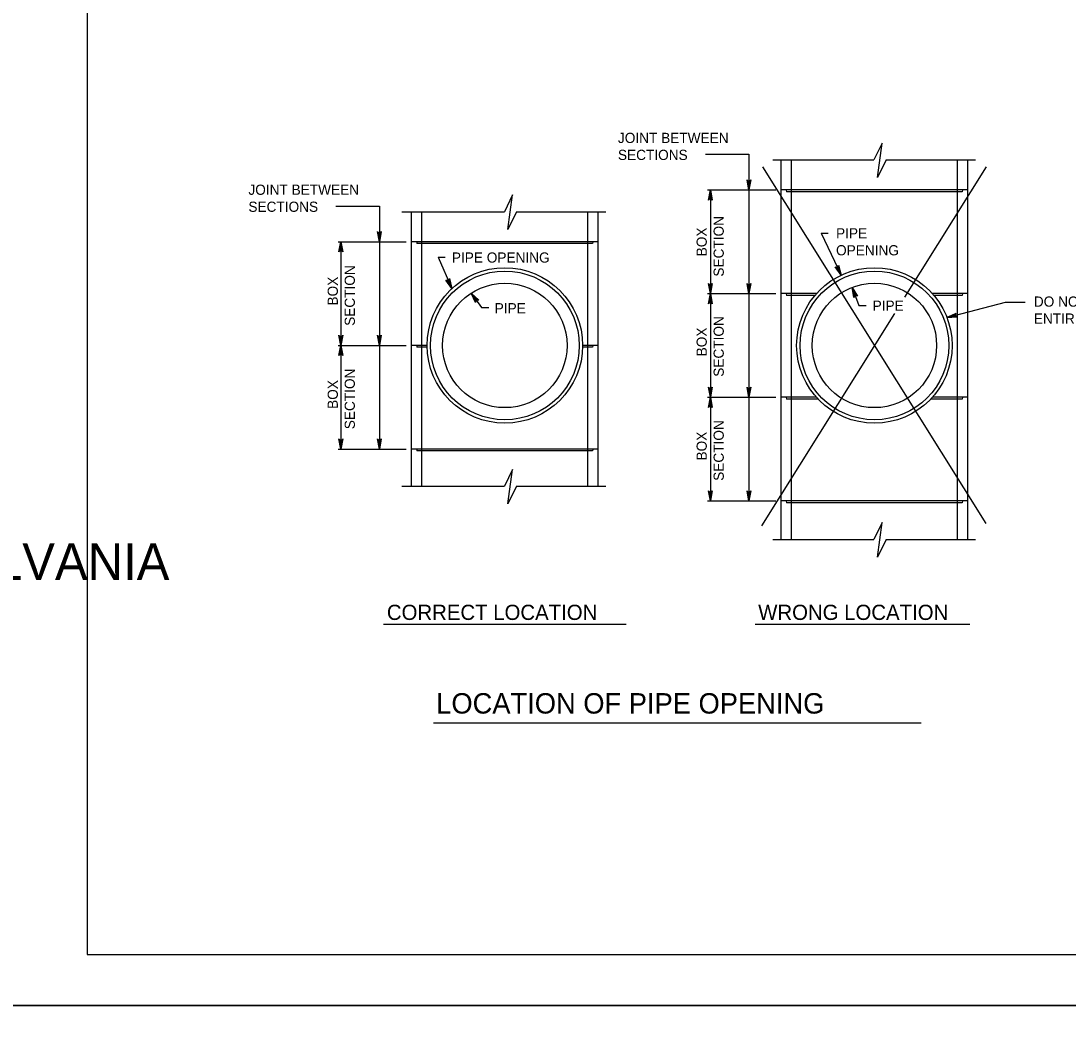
# Model space of a CAD drawing. Extents: x -6420 to 49575, y -4552 to 11624.
# Drawn here: x -838 to 172, y 5753 to 6727 of the extents above; entities that cross this region are included whole.
import ezdxf

# ---------------------------------------------------------------- set-up
doc = ezdxf.new("R2010")
doc.units = 0
doc.layers.add('1', color=7, linetype='Continuous')
doc.layers.add('PLT-BNDY', color=7, linetype='Continuous')

msp = doc.modelspace()

# ---------------------------------------------------------------- linework, layer by layer
at = {"layer": '1'}
for p, q in [((-177.6, 6598.6), (-135.7, 6598.6)), ((-135.7, 6598.6), (-135.7, 6264.2)), ((-122.6, 6586.4), (92.8, 6242.6)), ((-112.8, 6593.2), (-15.1, 6593.2)), ((-104.7, 6227.1), (-104.7, 6593.2)), ((-94.7, 6227.1), (-94.7, 6593.2)), ((-3.5, 6593.2), (82.7, 6593.2)), ((93.1, 6586.4), (14.4, 6460.7)), ((65.3, 6227.1), (65.3, 6593.2)), ((75.3, 6227.1), (75.3, 6593.2)), ((-175.6, 6564.2), (-109.7, 6564.2)), ((-172.9, 6564.2), (-172.9, 6464.2)), ((75.3, 6564.2), (-104.7, 6564.2)), ((-99.7, 6564.2), (-99.5, 6562.5)), ((70.1, 6562.5), (-99.5, 6562.5)), ((70.3, 6564.2), (70.1, 6562.5)), ((-534.2, 6548.6), (-492.2, 6548.6)), ((-492.2, 6548.6), (-492.2, 6314.2)), ((-470.6, 6543.2), (-371.6, 6543.2)), ((-461.2, 6278.4), (-461.2, 6543.2)), ((-451.2, 6278.4), (-451.2, 6543.2)), ((-360, 6543.2), (-273.7, 6543.2)), ((-291.2, 6278.4), (-291.2, 6543.2)), ((-281.2, 6278.4), (-281.2, 6543.2)), ((-66.1, 6522.5), (-59.3, 6522.5)), ((-66.1, 6522.5), (-46.9, 6482)), ((-532.1, 6514.2), (-466.3, 6514.2)), ((-529.5, 6514.2), (-529.5, 6414.2)), ((-281.2, 6514.2), (-461.2, 6514.2)), ((-456.2, 6514.2), (-456, 6512.5)), ((-286.5, 6512.5), (-456, 6512.5)), ((-286.2, 6514.2), (-286.5, 6512.5)), ((-435.6, 6499.4), (-428.8, 6499.4)), ((-435.6, 6499.4), (-422.4, 6469.1)), ((-36.3, 6470.2), (-29.6, 6452.9)), ((-403.7, 6464.7), (-393.6, 6450.9)), ((-175.6, 6464.2), (-109.7, 6464.2)), ((-172.9, 6464.2), (-172.9, 6364.2)), ((-70.6, 6464.2), (-104.7, 6464.2)), ((-99.7, 6464.2), (-99.5, 6462.5)), ((-72.1, 6462.5), (-99.5, 6462.5)), ((75.3, 6464.2), (41.2, 6464.2)), ((70.1, 6462.5), (42.6, 6462.5)), ((70.3, 6464.2), (70.1, 6462.5)), ((-393.6, 6450.9), (-386.8, 6450.9)), ((4.6, 6445.1), (-123.7, 6240.2)), ((-29.6, 6452.9), (-22.7, 6452.9)), ((-532.1, 6414.2), (-466.3, 6414.2)), ((-529.5, 6414.2), (-529.5, 6314.2)), ((-446.2, 6414.2), (-461.2, 6414.2)), ((-456.2, 6414.2), (-456, 6412.5)), ((-446.2, 6412.5), (-456, 6412.5)), ((-286.5, 6412.5), (-296.3, 6412.5)), ((-281.2, 6414.2), (-296.2, 6414.2)), ((-286.2, 6414.2), (-286.5, 6412.5)), ((-175.6, 6364.2), (-109.7, 6364.2)), ((-172.9, 6364.2), (-172.9, 6264.2)), ((-70.6, 6364.2), (-104.7, 6364.2)), ((-99.7, 6364.2), (-99.5, 6362.5)), ((75.3, 6364.2), (41.2, 6364.2)), ((70.3, 6364.2), (70.1, 6362.5)), ((-69.1, 6362.5), (-99.5, 6362.5)), ((70.1, 6362.5), (39.6, 6362.5)), ((-532.1, 6314.2), (-466.3, 6314.2)), ((-281.2, 6314.2), (-461.2, 6314.2)), ((-456.2, 6314.2), (-456, 6312.5)), ((-286.2, 6314.2), (-286.5, 6312.5)), ((-286.5, 6312.5), (-456, 6312.5)), ((-470.6, 6278.4), (-371.6, 6278.4)), ((-360, 6278.4), (-273.7, 6278.4)), ((-175.6, 6264.2), (-109.7, 6264.2)), ((75.3, 6264.2), (-104.7, 6264.2)), ((-99.7, 6264.2), (-99.5, 6262.5)), ((70.3, 6264.2), (70.1, 6262.5)), ((70.1, 6262.5), (-99.5, 6262.5)), ((-112.8, 6227.1), (-15.1, 6227.1)), ((-3.5, 6227.1), (82.7, 6227.1)), ((-488.3, 6145.2), (-254.3, 6145.2)), ((-129.6, 6145.2), (77.3, 6145.2)), ((-439.9, 6050.2), (30.4, 6050.2))]:
    msp.add_line(p, q, dxfattribs=at)
for points in [[(1804.7, 5826.7), (1804.7, 7677), (-774, 7677), (-774, 5826.7), (1804.7, 5826.7), (1804.7, 5913.1), (1148.5, 5913.1), (1148.5, 6125.3), (1804.7, 6125.3), (1804.7, 6220.4), (1148.5, 6220.4), (1148.5, 5826.7), (1407.1, 5826.7), (1407.1, 5913.1), (1407.1, 5826.7), (1659.7, 5826.7), (1659.7, 5913.1), (1659.7, 5872.7), (1804.7, 5872.7)], [(-3.5, 6593.2), (-11.8, 6576.1), (-7.3, 6609.4), (-15.1, 6593.2)], [(-135.7, 6564.2), (-137.5, 6574), (-137.3, 6573.6), (-137, 6573.2), (-136.7, 6573), (-136.3, 6572.9), (-136, 6572.8), (-135.7, 6572.7), (-135.4, 6572.8), (-135, 6572.9), (-134.7, 6573), (-134.4, 6573.2), (-134.1, 6573.6), (-133.8, 6574), (-135.7, 6564.2), (-134.1, 6573.6), (-134.4, 6573.2), (-135.7, 6564.2), (-134.7, 6573), (-135, 6572.9), (-135.7, 6564.2), (-135.4, 6572.8), (-135.7, 6572.7), (-135.7, 6564.2), (-136, 6572.8), (-136.3, 6572.9), (-135.7, 6564.2), (-136.7, 6573), (-137, 6573.2), (-135.7, 6564.2), (-137.3, 6573.6)], [(-360, 6543.2), (-368.4, 6526.1), (-363.8, 6559.4), (-371.6, 6543.2)], [(-172.9, 6564.2), (-171.1, 6554.4), (-171.4, 6554.8), (-171.6, 6555.2), (-171.9, 6555.4), (-172.3, 6555.6), (-172.6, 6555.6), (-172.9, 6555.7), (-173.3, 6555.6), (-173.6, 6555.6), (-173.9, 6555.4), (-174.2, 6555.2), (-174.5, 6554.8), (-174.8, 6554.4), (-172.9, 6564.2), (-174.5, 6554.8), (-174.2, 6555.2), (-172.9, 6564.2), (-173.9, 6555.4), (-173.6, 6555.6), (-172.9, 6564.2), (-173.3, 6555.6), (-172.9, 6555.7), (-172.9, 6564.2), (-172.6, 6555.6), (-172.3, 6555.6), (-172.9, 6564.2), (-171.9, 6555.4), (-171.6, 6555.2), (-172.9, 6564.2), (-171.4, 6554.8)], [(-492.2, 6514.2), (-494, 6524), (-493.8, 6523.6), (-493.5, 6523.2), (-493.2, 6523), (-492.9, 6522.9), (-492.5, 6522.8), (-492.2, 6522.7), (-491.9, 6522.8), (-491.6, 6522.9), (-491.2, 6523), (-490.9, 6523.2), (-490.6, 6523.6), (-490.4, 6524), (-492.2, 6514.2), (-490.6, 6523.6), (-490.9, 6523.2), (-492.2, 6514.2), (-491.2, 6523), (-491.6, 6522.9), (-492.2, 6514.2), (-491.9, 6522.8), (-492.2, 6522.7), (-492.2, 6514.2), (-492.5, 6522.8), (-492.9, 6522.9), (-492.2, 6514.2), (-493.2, 6523), (-493.5, 6523.2), (-492.2, 6514.2), (-493.8, 6523.6)], [(-529.5, 6514.2), (-527.6, 6504.4), (-527.9, 6504.8), (-528.1, 6505.2), (-528.5, 6505.4), (-528.8, 6505.6), (-529.1, 6505.6), (-529.5, 6505.7), (-529.8, 6505.6), (-530.1, 6505.6), (-530.4, 6505.4), (-530.8, 6505.2), (-531, 6504.8), (-531.3, 6504.4), (-529.5, 6514.2), (-531, 6504.8), (-530.8, 6505.2), (-529.5, 6514.2), (-530.4, 6505.4), (-530.1, 6505.6), (-529.5, 6514.2), (-529.8, 6505.6), (-529.5, 6505.7), (-529.5, 6514.2), (-529.1, 6505.6), (-528.8, 6505.6), (-529.5, 6514.2), (-528.5, 6505.4), (-528.1, 6505.2), (-529.5, 6514.2), (-527.9, 6504.8)], [(-46.9, 6482), (-52.7, 6490), (-52.3, 6489.8), (-51.9, 6489.6), (-51.6, 6489.5), (-51.2, 6489.5), (-50.9, 6489.6), (-50.5, 6489.7), (-50.3, 6489.9), (-50, 6490.1), (-49.8, 6490.4), (-49.6, 6490.7), (-49.5, 6491.1), (-49.4, 6491.6), (-46.9, 6482), (-49.5, 6491.1), (-49.6, 6490.7), (-46.9, 6482), (-49.8, 6490.4), (-50, 6490.1), (-46.9, 6482), (-50.3, 6489.9), (-50.5, 6489.7), (-46.9, 6482), (-50.9, 6489.6), (-51.2, 6489.5), (-46.9, 6482), (-51.6, 6489.5), (-51.9, 6489.6), (-46.9, 6482), (-52.3, 6489.8)], [(-422.4, 6469.1), (-428, 6477.3), (-427.6, 6477.1), (-427.2, 6476.8), (-426.8, 6476.8), (-426.5, 6476.7), (-426.1, 6476.8), (-425.8, 6476.9), (-425.5, 6477.1), (-425.2, 6477.2), (-425, 6477.6), (-424.8, 6477.9), (-424.7, 6478.3), (-424.6, 6478.8), (-422.4, 6469.1), (-424.7, 6478.3), (-424.8, 6477.9), (-422.4, 6469.1), (-425, 6477.6), (-425.2, 6477.2), (-422.4, 6469.1), (-425.5, 6477.1), (-425.8, 6476.9), (-422.4, 6469.1), (-426.1, 6476.8), (-426.5, 6476.7), (-422.4, 6469.1), (-426.8, 6476.8), (-427.2, 6476.8), (-422.4, 6469.1), (-427.6, 6477.1)], [(-172.9, 6464.2), (-174.8, 6474), (-174.5, 6473.6), (-174.2, 6473.2), (-173.9, 6473), (-173.6, 6472.9), (-173.3, 6472.8), (-172.9, 6472.7), (-172.6, 6472.8), (-172.3, 6472.9), (-171.9, 6473), (-171.6, 6473.2), (-171.4, 6473.6), (-171.1, 6474), (-172.9, 6464.2), (-171.4, 6473.6), (-171.6, 6473.2), (-172.9, 6464.2), (-171.9, 6473), (-172.3, 6472.9), (-172.9, 6464.2), (-172.6, 6472.8), (-172.9, 6472.7), (-172.9, 6464.2), (-173.3, 6472.8), (-173.6, 6472.9), (-172.9, 6464.2), (-173.9, 6473), (-174.2, 6473.2), (-172.9, 6464.2), (-174.5, 6473.6)], [(-135.7, 6464.2), (-137.5, 6474), (-137.3, 6473.6), (-137, 6473.2), (-136.7, 6473), (-136.3, 6472.9), (-136, 6472.8), (-135.7, 6472.7), (-135.4, 6472.8), (-135, 6472.9), (-134.7, 6473), (-134.4, 6473.2), (-134.1, 6473.6), (-133.8, 6474), (-135.7, 6464.2), (-134.1, 6473.6), (-134.4, 6473.2), (-135.7, 6464.2), (-134.7, 6473), (-135, 6472.9), (-135.7, 6464.2), (-135.4, 6472.8), (-135.7, 6472.7), (-135.7, 6464.2), (-136, 6472.8), (-136.3, 6472.9), (-135.7, 6464.2), (-136.7, 6473), (-137, 6473.2), (-135.7, 6464.2), (-137.3, 6473.6)], [(-36.3, 6470.2), (-31, 6461.7), (-31.4, 6462), (-31.8, 6462.3), (-32.2, 6462.3), (-32.5, 6462.4), (-32.9, 6462.3), (-33.2, 6462.3), (-33.5, 6462.1), (-33.8, 6461.9), (-34, 6461.6), (-34.2, 6461.3), (-34.3, 6460.9), (-34.5, 6460.4), (-36.3, 6470.2), (-34.3, 6460.9), (-34.2, 6461.3), (-36.3, 6470.2), (-34, 6461.6), (-33.8, 6461.9), (-36.3, 6470.2), (-33.5, 6462.1), (-33.2, 6462.3), (-36.3, 6470.2), (-32.9, 6462.3), (-32.5, 6462.4), (-36.3, 6470.2), (-32.2, 6462.3), (-31.8, 6462.3), (-36.3, 6470.2), (-31.4, 6462)], [(-403.7, 6464.7), (-396.4, 6457.9), (-396.9, 6458), (-397.3, 6458.2), (-397.7, 6458.1), (-398, 6458.1), (-398.3, 6458), (-398.6, 6457.8), (-398.9, 6457.6), (-399.1, 6457.3), (-399.3, 6457), (-399.4, 6456.6), (-399.4, 6456.2), (-399.4, 6455.7), (-403.7, 6464.7), (-399.4, 6456.2), (-399.4, 6456.6), (-403.7, 6464.7), (-399.3, 6457), (-399.1, 6457.3), (-403.7, 6464.7), (-398.9, 6457.6), (-398.6, 6457.8), (-403.7, 6464.7), (-398.3, 6458), (-398, 6458.1), (-403.7, 6464.7), (-397.7, 6458.1), (-397.3, 6458.2), (-403.7, 6464.7), (-396.9, 6458)], [(-172.9, 6464.2), (-171.1, 6454.4), (-171.4, 6454.8), (-171.6, 6455.2), (-171.9, 6455.4), (-172.3, 6455.6), (-172.6, 6455.6), (-172.9, 6455.7), (-173.3, 6455.6), (-173.6, 6455.6), (-173.9, 6455.4), (-174.2, 6455.2), (-174.5, 6454.8), (-174.8, 6454.4), (-172.9, 6464.2), (-174.5, 6454.8), (-174.2, 6455.2), (-172.9, 6464.2), (-173.9, 6455.4), (-173.6, 6455.6), (-172.9, 6464.2), (-173.3, 6455.6), (-172.9, 6455.7), (-172.9, 6464.2), (-172.6, 6455.6), (-172.3, 6455.6), (-172.9, 6464.2), (-171.9, 6455.4), (-171.6, 6455.2), (-172.9, 6464.2), (-171.4, 6454.8)], [(55.3, 6441.1), (111.7, 6455.8), (130.8, 6455.8)], [(55.3, 6441.1), (64.2, 6445.3), (63.9, 6445), (63.6, 6444.6), (63.5, 6444.2), (63.4, 6443.9), (63.5, 6443.6), (63.5, 6443.2), (63.6, 6442.9), (63.8, 6442.6), (64, 6442.4), (64.3, 6442.1), (64.7, 6441.9), (65.2, 6441.8), (55.3, 6441.1), (64.7, 6441.9), (64.3, 6442.1), (55.3, 6441.1), (64, 6442.4), (63.8, 6442.6), (55.3, 6441.1), (63.6, 6442.9), (63.5, 6443.2), (55.3, 6441.1), (63.5, 6443.6), (63.4, 6443.9), (55.3, 6441.1), (63.5, 6444.2), (63.6, 6444.6), (55.3, 6441.1), (63.9, 6445)], [(-529.5, 6414.2), (-531.3, 6424), (-531, 6423.6), (-530.8, 6423.2), (-530.4, 6423), (-530.1, 6422.9), (-529.8, 6422.8), (-529.5, 6422.7), (-529.1, 6422.8), (-528.8, 6422.9), (-528.5, 6423), (-528.1, 6423.2), (-527.9, 6423.6), (-527.6, 6424), (-529.5, 6414.2), (-527.9, 6423.6), (-528.1, 6423.2), (-529.5, 6414.2), (-528.5, 6423), (-528.8, 6422.9), (-529.5, 6414.2), (-529.1, 6422.8), (-529.5, 6422.7), (-529.5, 6414.2), (-529.8, 6422.8), (-530.1, 6422.9), (-529.5, 6414.2), (-530.4, 6423), (-530.8, 6423.2), (-529.5, 6414.2), (-531, 6423.6)], [(-492.2, 6414.2), (-494, 6424), (-493.8, 6423.6), (-493.5, 6423.2), (-493.2, 6423), (-492.9, 6422.9), (-492.5, 6422.8), (-492.2, 6422.7), (-491.9, 6422.8), (-491.6, 6422.9), (-491.2, 6423), (-490.9, 6423.2), (-490.6, 6423.6), (-490.4, 6424), (-492.2, 6414.2), (-490.6, 6423.6), (-490.9, 6423.2), (-492.2, 6414.2), (-491.2, 6423), (-491.6, 6422.9), (-492.2, 6414.2), (-491.9, 6422.8), (-492.2, 6422.7), (-492.2, 6414.2), (-492.5, 6422.8), (-492.9, 6422.9), (-492.2, 6414.2), (-493.2, 6423), (-493.5, 6423.2), (-492.2, 6414.2), (-493.8, 6423.6)], [(-529.5, 6414.2), (-527.6, 6404.4), (-527.9, 6404.8), (-528.1, 6405.2), (-528.5, 6405.4), (-528.8, 6405.6), (-529.1, 6405.6), (-529.5, 6405.7), (-529.8, 6405.6), (-530.1, 6405.6), (-530.4, 6405.4), (-530.8, 6405.2), (-531, 6404.8), (-531.3, 6404.4), (-529.5, 6414.2), (-531, 6404.8), (-530.8, 6405.2), (-529.5, 6414.2), (-530.4, 6405.4), (-530.1, 6405.6), (-529.5, 6414.2), (-529.8, 6405.6), (-529.5, 6405.7), (-529.5, 6414.2), (-529.1, 6405.6), (-528.8, 6405.6), (-529.5, 6414.2), (-528.5, 6405.4), (-528.1, 6405.2), (-529.5, 6414.2), (-527.9, 6404.8)], [(-172.9, 6364.2), (-174.8, 6374), (-174.5, 6373.6), (-174.2, 6373.2), (-173.9, 6373), (-173.6, 6372.9), (-173.3, 6372.8), (-172.9, 6372.7), (-172.6, 6372.8), (-172.3, 6372.9), (-171.9, 6373), (-171.6, 6373.2), (-171.4, 6373.6), (-171.1, 6374), (-172.9, 6364.2), (-171.4, 6373.6), (-171.6, 6373.2), (-172.9, 6364.2), (-171.9, 6373), (-172.3, 6372.9), (-172.9, 6364.2), (-172.6, 6372.8), (-172.9, 6372.7), (-172.9, 6364.2), (-173.3, 6372.8), (-173.6, 6372.9), (-172.9, 6364.2), (-173.9, 6373), (-174.2, 6373.2), (-172.9, 6364.2), (-174.5, 6373.6)], [(-135.7, 6364.2), (-137.5, 6374), (-137.3, 6373.6), (-137, 6373.2), (-136.7, 6373), (-136.3, 6372.9), (-136, 6372.8), (-135.7, 6372.7), (-135.4, 6372.8), (-135, 6372.9), (-134.7, 6373), (-134.4, 6373.2), (-134.1, 6373.6), (-133.8, 6374), (-135.7, 6364.2), (-134.1, 6373.6), (-134.4, 6373.2), (-135.7, 6364.2), (-134.7, 6373), (-135, 6372.9), (-135.7, 6364.2), (-135.4, 6372.8), (-135.7, 6372.7), (-135.7, 6364.2), (-136, 6372.8), (-136.3, 6372.9), (-135.7, 6364.2), (-136.7, 6373), (-137, 6373.2), (-135.7, 6364.2), (-137.3, 6373.6)], [(-172.9, 6364.2), (-171.1, 6354.4), (-171.4, 6354.8), (-171.6, 6355.2), (-171.9, 6355.4), (-172.3, 6355.6), (-172.6, 6355.6), (-172.9, 6355.7), (-173.3, 6355.6), (-173.6, 6355.6), (-173.9, 6355.4), (-174.2, 6355.2), (-174.5, 6354.8), (-174.8, 6354.4), (-172.9, 6364.2), (-174.5, 6354.8), (-174.2, 6355.2), (-172.9, 6364.2), (-173.9, 6355.4), (-173.6, 6355.6), (-172.9, 6364.2), (-173.3, 6355.6), (-172.9, 6355.7), (-172.9, 6364.2), (-172.6, 6355.6), (-172.3, 6355.6), (-172.9, 6364.2), (-171.9, 6355.4), (-171.6, 6355.2), (-172.9, 6364.2), (-171.4, 6354.8)], [(-529.5, 6314.2), (-531.3, 6324), (-531, 6323.6), (-530.8, 6323.2), (-530.4, 6323), (-530.1, 6322.9), (-529.8, 6322.8), (-529.5, 6322.7), (-529.1, 6322.8), (-528.8, 6322.9), (-528.5, 6323), (-528.1, 6323.2), (-527.9, 6323.6), (-527.6, 6324), (-529.5, 6314.2), (-527.9, 6323.6), (-528.1, 6323.2), (-529.5, 6314.2), (-528.5, 6323), (-528.8, 6322.9), (-529.5, 6314.2), (-529.1, 6322.8), (-529.5, 6322.7), (-529.5, 6314.2), (-529.8, 6322.8), (-530.1, 6322.9), (-529.5, 6314.2), (-530.4, 6323), (-530.8, 6323.2), (-529.5, 6314.2), (-531, 6323.6)], [(-492.2, 6314.2), (-494, 6324), (-493.8, 6323.6), (-493.5, 6323.2), (-493.2, 6323), (-492.9, 6322.9), (-492.5, 6322.8), (-492.2, 6322.7), (-491.9, 6322.8), (-491.6, 6322.9), (-491.2, 6323), (-490.9, 6323.2), (-490.6, 6323.6), (-490.4, 6324), (-492.2, 6314.2), (-490.6, 6323.6), (-490.9, 6323.2), (-492.2, 6314.2), (-491.2, 6323), (-491.6, 6322.9), (-492.2, 6314.2), (-491.9, 6322.8), (-492.2, 6322.7), (-492.2, 6314.2), (-492.5, 6322.8), (-492.9, 6322.9), (-492.2, 6314.2), (-493.2, 6323), (-493.5, 6323.2), (-492.2, 6314.2), (-493.8, 6323.6)], [(-360, 6278.4), (-368.4, 6261.4), (-363.8, 6294.7), (-371.6, 6278.4)], [(-172.9, 6264.2), (-174.8, 6274), (-174.5, 6273.6), (-174.2, 6273.2), (-173.9, 6273), (-173.6, 6272.9), (-173.3, 6272.8), (-172.9, 6272.7), (-172.6, 6272.8), (-172.3, 6272.9), (-171.9, 6273), (-171.6, 6273.2), (-171.4, 6273.6), (-171.1, 6274), (-172.9, 6264.2), (-171.4, 6273.6), (-171.6, 6273.2), (-172.9, 6264.2), (-171.9, 6273), (-172.3, 6272.9), (-172.9, 6264.2), (-172.6, 6272.8), (-172.9, 6272.7), (-172.9, 6264.2), (-173.3, 6272.8), (-173.6, 6272.9), (-172.9, 6264.2), (-173.9, 6273), (-174.2, 6273.2), (-172.9, 6264.2), (-174.5, 6273.6)], [(-135.7, 6264.2), (-137.5, 6274), (-137.3, 6273.6), (-137, 6273.2), (-136.7, 6273), (-136.3, 6272.9), (-136, 6272.8), (-135.7, 6272.7), (-135.4, 6272.8), (-135, 6272.9), (-134.7, 6273), (-134.4, 6273.2), (-134.1, 6273.6), (-133.8, 6274), (-135.7, 6264.2), (-134.1, 6273.6), (-134.4, 6273.2), (-135.7, 6264.2), (-134.7, 6273), (-135, 6272.9), (-135.7, 6264.2), (-135.4, 6272.8), (-135.7, 6272.7), (-135.7, 6264.2), (-136, 6272.8), (-136.3, 6272.9), (-135.7, 6264.2), (-136.7, 6273), (-137, 6273.2), (-135.7, 6264.2), (-137.3, 6273.6)], [(-3.5, 6227.1), (-11.8, 6210.1), (-7.3, 6243.4), (-15.1, 6227.1)]]:
    msp.add_lwpolyline(points, dxfattribs=at)
for centre, radius in [((-371.2, 6414.2), 75), ((-371.2, 6414.2), 71.7), ((-371.2, 6414.2), 71.7), ((-14.7, 6414.2), 75), ((-14.7, 6414.2), 71.7), ((-14.7, 6414.2), 71.7), ((-371.2, 6414.2), 60), ((-371.2, 6414.2), 60), ((-14.7, 6414.2), 60), ((-14.7, 6414.2), 60)]:
    msp.add_circle(centre, radius, dxfattribs=at)
at = {"layer": 'PLT-BNDY'}
for points in [[(-902, 7726.3), (1857.2, 7726.3), (1857.2, 5777.4), (-902, 5777.4)], [(-902, 5777.4), (1857.2, 5777.4), (1857.2, 3828.6), (-902, 3828.6)]]:
    msp.add_lwpolyline(points, close=True, dxfattribs=at)

# ---------------------------------------------------------------- texts
at = {"layer": '1'}
for s, height, p in [('JOINT BETWEEN', 9.843, (-262.1, 6609.5)), ('SECTIONS', 9.84, (-262.1, 6593.1)), ('JOINT BETWEEN', 9.843, (-618.6, 6559.5)), ('SECTIONS', 9.84, (-618.6, 6543.1)), ('PIPE', 9.84, (-51.7, 6517.5)), ('OPENING', 9.84, (-51.7, 6501.1)), ('PIPE OPENING', 9.843, (-422.3, 6494.1)), ('PIPE', 9.84, (-381, 6445.2)), ('PIPE', 9.84, (-16.4, 6447.6)), ('DO NOT VOID AN', 9.843, (139.1, 6451.6)), ('ENTIRE BOX SECTION', 9.843, (139.1, 6435.2)), ('COMMONWEALTH OF PENNSYLVANIA', 35.379, (-1567.5, 6188)), ('CORRECT LOCATION', 14.69, (-485, 6149.4)), ('WRONG LOCATION', 14.69, (-126.8, 6149.4)), ('LOCATION OF PIPE OPENING', 19.685, (-437.4, 6059.1))]:
    msp.add_text(s, height=height, dxfattribs=at).set_placement(p)
for s, p in [('SECTION', (-160, 6480.6)), ('BOX', (-176.4, 6500.2)), ('SECTION', (-515.9, 6433.1)), ('BOX', (-532.3, 6452.7)), ('SECTION', (-160, 6384)), ('BOX', (-176.4, 6403.7)), ('SECTION', (-515.9, 6333.4)), ('BOX', (-532.3, 6353)), ('SECTION', (-160, 6283.6)), ('BOX', (-176.4, 6303.2))]:
    msp.add_text(s, height=9.84, rotation=90, dxfattribs=at).set_placement(p)

doc.saveas('drawing.dxf')
